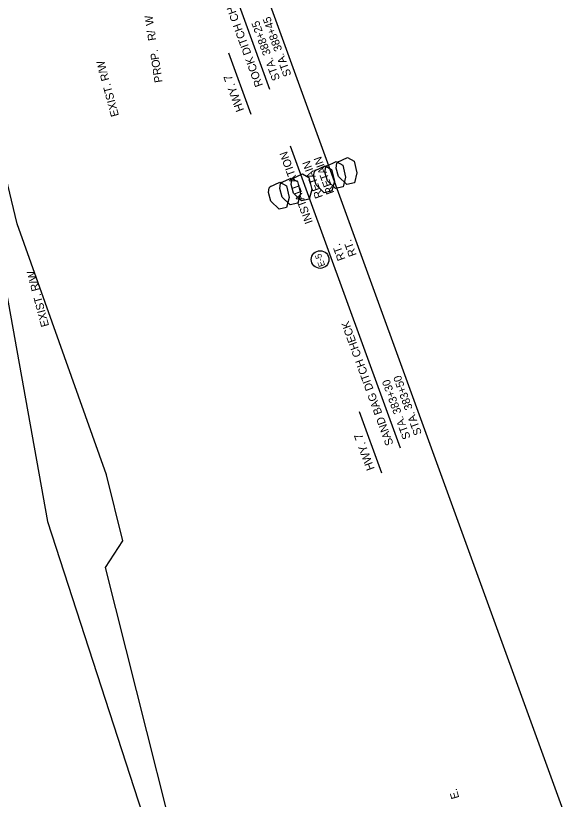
# Model space of a CAD drawing. Extents: x 960650 to 962115, y 1906901 to 1908757.
# Drawn here: x 961698 to 962115, y 1907282 to 1907870 of the extents above; entities that cross this region are included whole.
import ezdxf

# ---------------------------------------------------------------- set-up
doc = ezdxf.new("R2010")
doc.units = 0
for name, color, linetype in [('1', 7, 'Continuous'), ('44', 7, 'Continuous'), ('NO PLOT', 7, 'Continuous'), ('R_Draft', 7, 'Continuous'), ('S_TREE', 7, 'Continuous')]:
    doc.layers.add(name, color=color, linetype=linetype)

msp = doc.modelspace()

# ---------------------------------------------------------------- linework, layer by layer
at = {"layer": '1'}
msp.add_circle((961926.27, 1907686.91), 6.61, dxfattribs=at)
at = {"layer": '44'}
for p, q in [((961888.65, 1907814.33), (961806.22, 1908040.8)), ((961874.58, 1907795.7), (961857.87, 1907841.6)), ((961986.5, 1907545.48), (961904.07, 1907771.96)), ((961972.43, 1907526.86), (961955.72, 1907572.76))]:
    msp.add_line(p, q, dxfattribs=at)
at = {"layer": 'NO PLOT'}
msp.add_lwpolyline([(962114.55, 1907257.7), (961568.91, 1908756.85), (961079.18, 1908578.6), (961182.12, 1908295.76), (961245.55, 1908318.85), (961390.91, 1907919.48), (961327.48, 1907896.39), (961425.36, 1907627.47), (961483.4, 1907648.6), (961600.59, 1907326.6), (961542.56, 1907305.48), (961624.82, 1907079.46)], close=True, dxfattribs=at)
msp.add_lwpolyline([(962114.55, 1907257.7), (961568.91, 1908756.85), (961079.18, 1908578.6), (961182.12, 1908295.76), (961245.55, 1908318.85), (961390.91, 1907919.48), (961327.48, 1907896.39), (961425.36, 1907627.47), (961483.4, 1907648.6), (961600.59, 1907326.6), (961542.56, 1907305.48), (961624.82, 1907079.46)], close=True, dxfattribs=at)
msp.add_lwpolyline([(962114.55, 1907257.7), (961568.91, 1908756.85), (961079.18, 1908578.6), (961182.12, 1908295.76), (961245.55, 1908318.85), (961390.91, 1907919.48), (961327.48, 1907896.39), (961425.36, 1907627.47), (961483.4, 1907648.6), (961600.59, 1907326.6), (961542.56, 1907305.48), (961624.82, 1907079.46)], close=True, dxfattribs=at)
msp.add_lwpolyline([(962114.55, 1907257.7), (961568.91, 1908756.85), (961079.18, 1908578.6), (961182.12, 1908295.76), (961245.55, 1908318.85), (961390.91, 1907919.48), (961327.48, 1907896.39), (961425.36, 1907627.47), (961483.4, 1907648.6), (961600.59, 1907326.6), (961542.56, 1907305.48), (961624.82, 1907079.46)], close=True, dxfattribs=at)
msp.add_lwpolyline([(961546.11, 1908053.77), (961660.88, 1907856.14), (961665.4, 1907852.91), (961665.4, 1907852.91), (961672.08, 1907797.08), (961685.77, 1907691.1), (961721.87, 1907490.67), (961833.17, 1907148.06), (961842.49, 1907149.72), (961765.53, 1907456.14), (961778.4, 1907476.17), (961766.21, 1907525.48), (961699.17, 1907713.63), (961665.82, 1907852.62), (961665.4, 1907852.91), (961665.4, 1907852.91), (961665.39, 1907852.96), (961665.26, 1907853.71), (961666.04, 1907863.2), (961658.05, 1907894.81)], dxfattribs=at)
at = {"layer": 'S_TREE'}
for points in [[(961939.4, 1907759.92), (961946.88, 1907763.41), (961951.7, 1907760.67), (961953.85, 1907751.84), (961951.92, 1907744.46), (961946.22, 1907743.19), (961940.14, 1907749.07), (961938.28, 1907755.52), (961938.89, 1907759.17), (961940.08, 1907760.4)], [(961939.4, 1907759.92), (961946.88, 1907763.41), (961951.7, 1907760.67), (961953.85, 1907751.84), (961951.92, 1907744.46), (961946.22, 1907743.19), (961940.14, 1907749.07), (961938.28, 1907755.52), (961938.89, 1907759.17), (961940.08, 1907760.4)], [(961939.4, 1907759.92), (961946.88, 1907763.41), (961951.7, 1907760.67), (961953.85, 1907751.84), (961951.92, 1907744.46), (961946.22, 1907743.19), (961940.14, 1907749.07), (961938.28, 1907755.52), (961938.89, 1907759.17), (961940.08, 1907760.4)], [(961939.4, 1907759.92), (961946.88, 1907763.41), (961951.7, 1907760.67), (961953.85, 1907751.84), (961951.92, 1907744.46), (961946.22, 1907743.19), (961940.14, 1907749.07), (961938.28, 1907755.52), (961938.89, 1907759.17), (961940.08, 1907760.4)], [(961922.49, 1907753.76), (961929.96, 1907757.25), (961934.79, 1907754.52), (961936.94, 1907745.69), (961935, 1907738.31), (961929.3, 1907737.03), (961923.22, 1907742.92), (961921.36, 1907749.36), (961921.98, 1907753.02), (961923.17, 1907754.24)], [(961922.49, 1907753.76), (961929.96, 1907757.25), (961934.79, 1907754.52), (961936.94, 1907745.69), (961935, 1907738.31), (961929.3, 1907737.03), (961923.22, 1907742.92), (961921.36, 1907749.36), (961921.98, 1907753.02), (961923.17, 1907754.24)], [(961922.49, 1907753.76), (961929.96, 1907757.25), (961934.79, 1907754.52), (961936.94, 1907745.69), (961935, 1907738.31), (961929.3, 1907737.03), (961923.22, 1907742.92), (961921.36, 1907749.36), (961921.98, 1907753.02), (961923.17, 1907754.24)], [(961922.49, 1907753.76), (961929.96, 1907757.25), (961934.79, 1907754.52), (961936.94, 1907745.69), (961935, 1907738.31), (961929.3, 1907737.03), (961923.22, 1907742.92), (961921.36, 1907749.36), (961921.98, 1907753.02), (961923.17, 1907754.24)], [(961930.95, 1907756.84), (961938.42, 1907760.33), (961943.25, 1907757.59), (961945.4, 1907748.77), (961943.46, 1907741.38), (961937.76, 1907740.11), (961931.68, 1907746), (961929.82, 1907752.44), (961930.43, 1907756.1), (961931.63, 1907757.32)], [(961930.95, 1907756.84), (961938.42, 1907760.33), (961943.25, 1907757.59), (961945.4, 1907748.77), (961943.46, 1907741.38), (961937.76, 1907740.11), (961931.68, 1907746), (961929.82, 1907752.44), (961930.43, 1907756.1), (961931.63, 1907757.32)], [(961930.95, 1907756.84), (961938.42, 1907760.33), (961943.25, 1907757.59), (961945.4, 1907748.77), (961943.46, 1907741.38), (961937.76, 1907740.11), (961931.68, 1907746), (961929.82, 1907752.44), (961930.43, 1907756.1), (961931.63, 1907757.32)], [(961930.95, 1907756.84), (961938.42, 1907760.33), (961943.25, 1907757.59), (961945.4, 1907748.77), (961943.46, 1907741.38), (961937.76, 1907740.11), (961931.68, 1907746), (961929.82, 1907752.44), (961930.43, 1907756.1), (961931.63, 1907757.32)], [(961905.57, 1907747.61), (961913.05, 1907751.09), (961917.88, 1907748.36), (961920.02, 1907739.53), (961918.09, 1907732.15), (961912.39, 1907730.88), (961906.31, 1907736.76), (961904.45, 1907743.21), (961905.06, 1907746.86), (961906.26, 1907748.08)], [(961905.57, 1907747.61), (961913.05, 1907751.09), (961917.88, 1907748.36), (961920.02, 1907739.53), (961918.09, 1907732.15), (961912.39, 1907730.88), (961906.31, 1907736.76), (961904.45, 1907743.21), (961905.06, 1907746.86), (961906.26, 1907748.08)], [(961897.12, 1907744.53), (961904.59, 1907748.01), (961909.42, 1907745.28), (961911.57, 1907736.45), (961909.63, 1907729.07), (961903.93, 1907727.8), (961897.85, 1907733.68), (961895.99, 1907740.13), (961896.6, 1907743.78), (961897.8, 1907745)], [(961897.12, 1907744.53), (961904.59, 1907748.01), (961909.42, 1907745.28), (961911.57, 1907736.45), (961909.63, 1907729.07), (961903.93, 1907727.8), (961897.85, 1907733.68), (961895.99, 1907740.13), (961896.6, 1907743.78), (961897.8, 1907745)], [(961888.66, 1907741.45), (961896.13, 1907744.94), (961900.96, 1907742.2), (961903.11, 1907733.38), (961901.18, 1907725.99), (961895.47, 1907724.72), (961889.39, 1907730.61), (961887.54, 1907737.05), (961888.15, 1907740.71), (961889.34, 1907741.93)], [(961888.66, 1907741.45), (961896.13, 1907744.94), (961900.96, 1907742.2), (961903.11, 1907733.38), (961901.18, 1907725.99), (961895.47, 1907724.72), (961889.39, 1907730.61), (961887.54, 1907737.05), (961888.15, 1907740.71), (961889.34, 1907741.93)]]:
    msp.add_lwpolyline(points, dxfattribs=at)

# ---------------------------------------------------------------- texts
at = {"layer": '1'}
msp.add_text('E-5 ', height=4.8, rotation=110, dxfattribs=at).set_placement((961930.11, 1907682.46))
at = {"layer": '44'}
for s, height, p in [('ROCK DITCH CHECK', 6, (961883.48, 1907817.55)), ('STA. 388+45', 6, (961904.79, 1907825.3)), ('STA. 388+25', 6, (961896.33, 1907822.22)), ('HWY. 7', 6.25, (961869.37, 1907798.96)), ('INSTALLATION', 6, (961920.85, 1907714.89)), ('RETAIN', 6, (961936.93, 1907737.04)), ('RETAIN', 6, (961928.47, 1907733.96)), ('RT.', 6, (961945.28, 1907687.3)), ('RT.', 6, (961953.74, 1907690.38)), ('SAND BAG DITCH CHECK', 6, (961981.33, 1907548.71)), ('STA. 383+50', 6, (962002.64, 1907556.46)), ('STA. 383+30', 6, (961994.18, 1907553.38)), ('HWY. 7', 6.25, (961967.22, 1907530.12))]:
    msp.add_text(s, height=height, rotation=110, dxfattribs=at).set_placement(p)
at = {"layer": 'R_Draft'}
for s, rotation, p in [('W', 98.68221, (961801.69, 1907862.78)), ('/', 98.68221, (961802.58, 1907856.99)), ('R', 98.68221, (961803.43, 1907851.39)), ('P', 98.68221, (961805.64, 1907836.96)), ('.', 98.68221, (961804.78, 1907842.56)), ('EXIST. R/W', 105.0127, (961775.51, 1907794.86)), ('O', 98.68221, (961806.52, 1907831.17)), ('R', 98.68221, (961807.38, 1907825.56)), ('P', 98.68221, (961808.23, 1907819.96)), ('EXIST. R/W', 104.76842, (961723.16, 1907637.3)), ('E', 105.81657, (962030.6, 1907283.5)), ('.', 105.81657, (962029.13, 1907288.68))]:
    msp.add_text(s, height=6, rotation=rotation, dxfattribs=at).set_placement(p)

doc.saveas('drawing.dxf')
